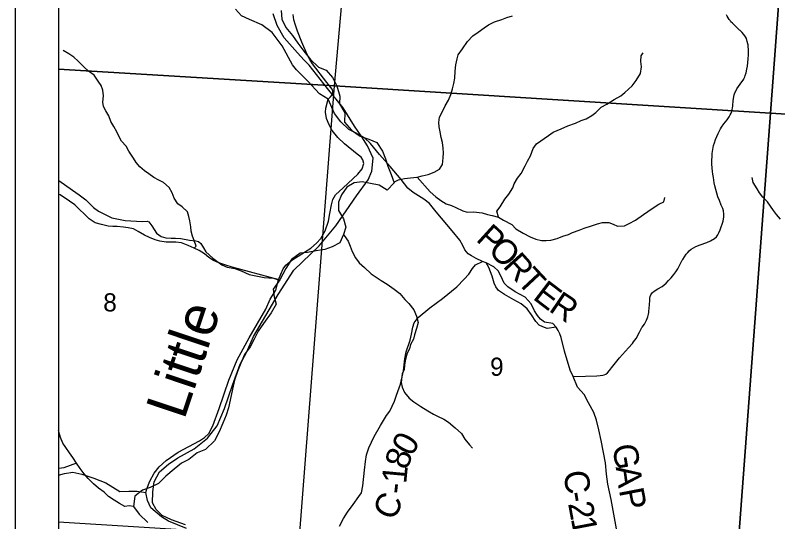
# Model space of a CAD drawing. Extents: x 0 to 34, y 0 to 22.
# Drawn here: x 2 to 3.758, y 17.554 to 18.721 of the extents above; entities that cross this region are included whole.
import ezdxf

# ---------------------------------------------------------------- set-up
doc = ezdxf.new("R2010")
doc.units = 0
for name, color, linetype in [('GM_X_Corporation', 7, 'Continuous'), ('GM_X_County_Road', 7, 'Continuous'), ('GM_X_County_Road_Text', 7, 'Continuous'), ('GM_X_Minor_River', 7, 'Continuous'), ('GM_X_Minor_River_Text', 7, 'Continuous'), ('GM_X_Rail_Line', 7, 'Continuous'), ('GM_X_Section_Text', 7, 'Continuous'), ('GM_X_Township_Road', 7, 'Continuous'), ('SH_Data', 7, 'Continuous')]:
    doc.layers.add(name, color=color, linetype=linetype)

msp = doc.modelspace()

# ---------------------------------------------------------------- linework, layer by layer
at = {"layer": 'GM_X_Corporation'}
for points in [[(3.3441, 14.1), (8.9, 14.1), (8.9, 20.9), (2.1, 20.9), (2.1, 16.1353), (2.1457, 16.065), (2.3447, 15.6926), (2.4297, 15.5215), (2.465, 15.4504), (2.4884, 15.4033), (2.5769, 15.2135), (2.7849, 14.8403), (2.8931, 14.6544), (3.0297, 14.4867), (3.1386, 14.3654), (3.228, 14.2415)], [(2.1, 19.629), (2.1, 18.5966), (2.7366, 18.558), (2.8266, 19.5815)], [(2.8266, 19.5815), (3.8179, 19.5177), (3.742, 18.4953), (2.7366, 18.558)], [(3.8179, 19.5177), (4.8445, 19.4512), (4.7598, 18.4308), (3.742, 18.4953)], [(2.1, 18.5966), (2.1, 17.5535), (2.6553, 17.519), (2.7366, 18.558)], [(3.742, 18.4953), (3.6641, 17.4586), (2.6553, 17.519), (2.7366, 18.558)], [(4.7598, 18.4308), (4.6804, 17.3872), (3.6641, 17.4586), (3.742, 18.4953)]]:
    msp.add_lwpolyline(points, close=True, dxfattribs=at)
msp.add_lwpolyline([(6.7043, 17.4985), (6.7536, 18.2991), (6.7629, 18.3924), (6.7876, 18.7583), (6.824, 19.3005), (6.5423, 19.3229), (5.9419, 19.3649), (5.6539, 19.3859), (5.0201, 19.4401), (4.8375, 19.4557), (3.8692, 19.5228), (3.8201, 19.5262), (3.0215, 19.5789), (2.5886, 19.6074), (2.105, 19.6393), (2.1, 19.6396), (2.1, 16.1353)], dxfattribs=at)
at = {"layer": 'GM_X_County_Road'}
for points in [[(2.7215, 18.5278), (2.7014, 18.5397), (2.6747, 18.5691), (2.6483, 18.5951), (2.6393, 18.6066), (2.6157, 18.6508), (2.5928, 18.6813), (2.569, 18.6989), (2.5402, 18.7113), (2.5221, 18.7197), (2.5078, 18.7347)], [(3.2864, 17.8884), (3.3149, 17.889), (3.3412, 17.8899), (3.3491, 17.8903), (3.3554, 17.8916), (3.3585, 17.8924), (3.3622, 17.894), (3.3658, 17.8968), (3.3704, 17.9024), (3.3751, 17.9086), (3.3935, 17.9312), (3.4144, 17.9544), (3.4234, 17.9642), (3.4257, 17.9679), (3.4316, 17.9762), (3.4397, 17.9902), (3.4453, 18.0012), (3.4457, 18.0018), (3.4511, 18.0093), (3.4556, 18.0184), (3.4586, 18.0256), (3.4604, 18.0319), (3.4611, 18.0355), (3.4615, 18.0383), (3.4626, 18.0533), (3.4633, 18.0643), (3.4637, 18.0689), (3.4645, 18.0729), (3.4658, 18.0766), (3.4677, 18.0791), (3.4699, 18.0819), (3.4732, 18.0847), (3.4821, 18.0903), (3.4921, 18.0959), (3.4963, 18.0992), (3.5008, 18.1031), (3.5069, 18.1094), (3.5128, 18.1156), (3.5189, 18.1232), (3.5237, 18.1295), (3.5278, 18.1363), (3.5357, 18.152), (3.5384, 18.1563), (3.5393, 18.1578), (3.5475, 18.17), (3.5508, 18.1742), (3.5545, 18.1779), (3.5591, 18.1819), (3.5639, 18.1849), (3.5694, 18.1877), (3.5792, 18.1917), (3.5948, 18.197), (3.6037, 18.2007), (3.6129, 18.2063), (3.6172, 18.2102), (3.6202, 18.2145), (3.6227, 18.2198), (3.6259, 18.2266), (3.6323, 18.2464), (3.6338, 18.2562), (3.6341, 18.2626), (3.6332, 18.2699), (3.6315, 18.2756), (3.6281, 18.2834), (3.6238, 18.2943), (3.6206, 18.3022), (3.618, 18.3106), (3.6157, 18.3191), (3.6136, 18.3277), (3.6121, 18.3345), (3.6102, 18.3467), (3.6091, 18.3546), (3.6082, 18.3606), (3.6073, 18.3693), (3.6065, 18.3779), (3.6065, 18.3878), (3.6069, 18.3943), (3.6076, 18.402), (3.6087, 18.4113), (3.6104, 18.4209), (3.6123, 18.4266), (3.6149, 18.4345), (3.6207, 18.4485), (3.6263, 18.4589), (3.6288, 18.4626), (3.6345, 18.4703), (3.6381, 18.475), (3.6419, 18.4802), (3.6462, 18.4869), (3.649, 18.4914), (3.6508, 18.4952), (3.6522, 18.499), (3.6534, 18.5034), (3.6544, 18.507), (3.655, 18.5121), (3.6559, 18.5243), (3.6564, 18.5282), (3.6573, 18.5336), (3.6583, 18.5377), (3.6598, 18.5419), (3.6609, 18.5445), (3.6644, 18.5511), (3.6758, 18.5676), (3.6762, 18.5682), (3.6799, 18.5737), (3.6806, 18.5746), (3.6826, 18.5788), (3.6837, 18.5821), (3.6855, 18.5882), (3.6871, 18.5965), (3.6886, 18.6038), (3.6896, 18.612), (3.6905, 18.6206), (3.6912, 18.6294), (3.6912, 18.6338), (3.6912, 18.6388), (3.6912, 18.6428), (3.6906, 18.6481), (3.69, 18.6528), (3.6896, 18.6551), (3.6882, 18.6606), (3.6862, 18.6671), (3.6842, 18.6708), (3.6823, 18.6738), (3.6795, 18.6777), (3.6763, 18.6814), (3.6715, 18.6859), (3.6703, 18.6869), (3.6587, 18.698), (3.6538, 18.7024), (3.6505, 18.706), (3.6485, 18.7085), (3.6467, 18.7111), (3.6442, 18.715), (3.6422, 18.7185), (3.6403, 18.7218)], [(2.3948, 17.5379), (2.3536, 17.5545), (2.3371, 17.5647), (2.3125, 17.5855), (2.305, 17.6026), (2.3014, 17.6208), (2.3038, 17.6295), (2.3101, 17.6469), (2.3202, 17.6654), (2.3322, 17.6804), (2.3483, 17.695), (2.3758, 17.7136), (2.4247, 17.7402), (2.4366, 17.748), (2.4462, 17.757), (2.4556, 17.7743), (2.4706, 17.8143), (2.4927, 17.8797), (2.5116, 17.9266), (2.5397, 17.9774), (2.5778, 18.0434), (2.588, 18.0668), (2.593, 18.075), (2.6012, 18.0871), (2.6072, 18.1113), (2.6127, 18.1241), (2.6178, 18.1366), (2.624, 18.1452), (2.6382, 18.1564), (2.6814, 18.1839), (2.6948, 18.1955), (2.7045, 18.2067), (2.7146, 18.2241), (2.7221, 18.2464), (2.7258, 18.2642), (2.7291, 18.2842), (2.7327, 18.2964), (2.7385, 18.3069), (2.7566, 18.3233), (2.7904, 18.3544), (2.8001, 18.3672), (2.8036, 18.3789), (2.8019, 18.3873), (2.7978, 18.3938), (2.7888, 18.4011), (2.7596, 18.4243), (2.7443, 18.4394), (2.7309, 18.4555), (2.7243, 18.4685), (2.7181, 18.4827), (2.7156, 18.4975), (2.7165, 18.507), (2.7215, 18.5278)], [(3.0775, 18.1536), (3.0633, 18.1605), (3.0521, 18.1661), (3.0443, 18.1709), (3.037, 18.1802), (3.032, 18.1906), (3.0251, 18.2026), (3.0075, 18.224), (2.9709, 18.2677), (2.9555, 18.2867), (2.9425, 18.297), (2.9176, 18.3122), (2.9054, 18.322), (2.89, 18.3426), (2.8647, 18.3726), (2.8398, 18.4003), (2.8189, 18.4256), (2.8056, 18.4385), (2.7847, 18.4498), (2.7694, 18.4579), (2.7506, 18.4751), (2.736, 18.4942), (2.7215, 18.5278)], [(2.7479, 17.5433), (2.7568, 17.5612), (2.7659, 17.5758), (2.7793, 17.5932), (2.7927, 17.6115), (2.7983, 17.6204), (2.8018, 17.6366), (2.8051, 17.6726), (2.8076, 17.6923), (2.8103, 17.7078), (2.8157, 17.7236), (2.8278, 17.7502), (2.8422, 17.7753), (2.8565, 17.7984), (2.8636, 17.8081), (2.8696, 17.8197), (2.8745, 17.8317), (2.8795, 17.8456), (2.8881, 17.8708), (2.8951, 17.9014), (2.8986, 17.9294), (2.9013, 17.9449), (2.9104, 17.972), (2.9138, 17.9855), (2.9166, 18.0018), (2.9203, 18.0123), (2.929, 18.0242), (2.9558, 18.0466), (2.9852, 18.0678), (3.0186, 18.0953), (3.0354, 18.1123), (3.0463, 18.1241), (3.0547, 18.1371), (3.0617, 18.1453), (3.0775, 18.1536)], [(3.3864, 17.5373), (3.374, 17.6045), (3.3667, 17.6404), (3.3639, 17.6633), (3.3616, 17.6892), (3.3509, 17.741), (3.3455, 17.7651), (3.3401, 17.7877), (3.3347, 17.8054), (3.3224, 17.8278), (3.3118, 17.8468), (3.297, 17.8635), (3.2864, 17.8884), (3.2796, 17.9031), (3.267, 17.9465), (3.2587, 17.9785), (3.256, 17.9866), (3.2523, 17.9945), (3.2474, 18.0021), (3.2269, 17.9987), (3.2168, 18.0024), (3.2082, 18.0069), (3.2005, 18.0154), (3.1903, 18.0306), (3.1805, 18.0441), (3.1668, 18.0559), (3.1496, 18.0648), (3.128, 18.0772), (3.1146, 18.0867), (3.108, 18.0949), (3.1045, 18.1034), (3.0996, 18.1199), (3.0923, 18.1398), (3.0857, 18.1499), (3.0775, 18.1536)]]:
    msp.add_lwpolyline(points, dxfattribs=at)
at = {"layer": 'GM_X_Minor_River'}
for points in [[(2.6132, 18.7321), (2.615, 18.7116), (2.6237, 18.6925), (2.6395, 18.6746), (2.6516, 18.6568), (2.6659, 18.6385), (2.681, 18.6191), (2.6992, 18.6015), (2.717, 18.5947), (2.7313, 18.5776), (2.7419, 18.5581), (2.7482, 18.5345), (2.7478, 18.517), (2.7599, 18.4957), (2.7595, 18.4748), (2.7757, 18.4561), (2.7957, 18.4424), (2.8154, 18.4352), (2.8339, 18.4279), (2.8471, 18.4077), (2.8535, 18.3902), (2.8592, 18.3727), (2.8671, 18.3537), (2.8735, 18.3347), (2.8579, 18.3176), (2.8394, 18.3294), (2.8189, 18.3332), (2.8, 18.3366), (2.7815, 18.3344), (2.7644, 18.3249), (2.7523, 18.307), (2.7454, 18.2899), (2.7457, 18.2708), (2.7567, 18.2518), (2.7627, 18.2324), (2.757, 18.2153), (2.7482, 18.1966), (2.7312, 18.1871), (2.7137, 18.1807), (2.694, 18.178), (2.6743, 18.1742), (2.6569, 18.1727), (2.6372, 18.1583), (2.6239, 18.137), (2.6098, 18.1108), (2.5947, 18.0898), (2.5973, 18.0723), (2.6018, 18.0548), (2.5904, 18.0347), (2.5725, 18.0107), (2.56, 17.9924), (2.5512, 17.9742), (2.5417, 17.9567), (2.5284, 17.9388), (2.5201, 17.9187), (2.5128, 17.8996), (2.506, 17.8802), (2.501, 17.8593), (2.4953, 17.8334), (2.4918, 17.8163), (2.4861, 17.7992), (2.4785, 17.7806), (2.4701, 17.7604), (2.4595, 17.7399), (2.4386, 17.7201), (2.4193, 17.7125), (2.4003, 17.6973), (2.3832, 17.6889), (2.3662, 17.6745), (2.3476, 17.6585), (2.3301, 17.6414), (2.3108, 17.6323), (2.2938, 17.6266), (2.2759, 17.6122), (2.2729, 17.589), (2.2857, 17.5711), (2.3061, 17.5516)], [(2.8735, 18.3347), (2.8743, 18.3367), (2.8841, 18.3416), (2.8974, 18.3446), (2.9113, 18.3462), (2.9268, 18.3481), (2.9382, 18.3507), (2.9522, 18.3542), (2.9658, 18.3591), (2.9783, 18.3663), (2.9851, 18.377), (2.987, 18.3925), (2.9873, 18.4039), (2.987, 18.4149), (2.9851, 18.4274), (2.9824, 18.4388), (2.9802, 18.4525), (2.9779, 18.4635), (2.9771, 18.4737), (2.9787, 18.4863), (2.9836, 18.4961), (2.9911, 18.5121), (2.9995, 18.525), (3.0048, 18.5379), (3.0085, 18.5512), (3.0112, 18.5633), (3.0138, 18.5762), (3.0142, 18.5922), (3.0157, 18.6066), (3.0191, 18.6202), (3.0218, 18.6297), (3.0312, 18.6438), (3.0433, 18.6601), (3.0551, 18.6734), (3.0679, 18.6818), (3.0811, 18.692), (3.0913, 18.6992), (3.105, 18.7061), (3.122, 18.711), (3.1337, 18.7156), (3.1469, 18.7198)], [(2.4127, 18.1842), (2.4169, 18.1887), (2.4127, 18.2016), (2.4086, 18.2119), (2.4055, 18.2229), (2.4048, 18.2331), (2.4025, 18.2468), (2.4006, 18.2571), (2.3972, 18.2681), (2.3851, 18.2791), (2.3753, 18.2866), (2.3662, 18.2992), (2.3617, 18.3117), (2.3549, 18.3242), (2.3417, 18.3352), (2.3311, 18.3405), (2.3198, 18.3473), (2.308, 18.3557), (2.2982, 18.3625), (2.2873, 18.3716), (2.2789, 18.3815), (2.2725, 18.3917), (2.2616, 18.4073), (2.2555, 18.4194), (2.2449, 18.4308), (2.2396, 18.441), (2.2343, 18.4524), (2.2272, 18.4642), (2.2204, 18.4763), (2.2155, 18.4892), (2.209, 18.501), (2.2034, 18.5108), (2.2022, 18.5207), (2.2037, 18.5351), (2.2022, 18.5484), (2.1981, 18.559), (2.1913, 18.5693), (2.1818, 18.5829), (2.169, 18.592), (2.1584, 18.6019), (2.1452, 18.6148), (2.135, 18.6246), (2.1236, 18.6318), (2.1108, 18.6398)], [(3.1143, 18.2552), (3.1109, 18.2696), (3.1181, 18.2795), (3.1287, 18.297), (3.1385, 18.3084), (3.1476, 18.3228), (3.1506, 18.3323), (3.1582, 18.3452), (3.1665, 18.3562), (3.176, 18.3737), (3.1816, 18.3843), (3.1884, 18.3972), (3.1945, 18.4139), (3.2024, 18.4249), (3.2296, 18.4435), (3.2402, 18.4515), (3.2588, 18.4595), (3.2743, 18.4663), (3.292, 18.4724), (3.3049, 18.4781), (3.317, 18.4823), (3.3294, 18.4895), (3.3393, 18.4971), (3.3514, 18.5089), (3.3642, 18.5161), (3.3816, 18.5267), (3.3964, 18.5351), (3.4062, 18.5431), (3.4228, 18.5583), (3.4323, 18.5704), (3.4417, 18.5864), (3.444, 18.6019), (3.4425, 18.6141), (3.4433, 18.6277), (3.4482, 18.6346)], [(2.9268, 18.3481), (2.9567, 18.3136), (2.9699, 18.3022), (2.9816, 18.2938), (2.9941, 18.2859), (3.0058, 18.2821), (3.0157, 18.2775), (3.0323, 18.27), (3.0421, 18.2669), (3.0565, 18.2677), (3.0765, 18.2654), (3.0894, 18.2616), (3.0996, 18.2594), (3.1143, 18.2552), (3.126, 18.2488), (3.1449, 18.2385), (3.1544, 18.2287), (3.1714, 18.2188), (3.1873, 18.2105), (3.2005, 18.2048), (3.2137, 18.2014), (3.2247, 18.2021), (3.2353, 18.2029), (3.25, 18.2063), (3.2632, 18.212), (3.2757, 18.2158), (3.2855, 18.2204), (3.3007, 18.2257), (3.3124, 18.2299), (3.3286, 18.2352), (3.3426, 18.2405), (3.3544, 18.2432), (3.3691, 18.2432), (3.3789, 18.2394), (3.3891, 18.2349), (3.405, 18.2357), (3.416, 18.2406), (3.4307, 18.249), (3.4492, 18.2619), (3.4689, 18.2752), (3.484, 18.2854), (3.4954, 18.2911), (3.4984, 18.301)], [(3.7649, 18.2507), (3.7558, 18.2613), (3.749, 18.2712), (3.7414, 18.2806), (3.7346, 18.2909), (3.7241, 18.3019), (3.7165, 18.3114), (3.7108, 18.3209), (3.7018, 18.3353), (3.6991, 18.347)], [(2.6086, 18.1111), (2.5004, 18.1402), (2.4857, 18.1448), (2.4698, 18.1504), (2.4573, 18.1558), (2.4467, 18.1626), (2.4361, 18.1709), (2.4241, 18.1789), (2.4127, 18.1842), (2.3987, 18.1906), (2.3836, 18.1963), (2.37, 18.1978), (2.3594, 18.1978), (2.3481, 18.1982), (2.3333, 18.2001), (2.3224, 18.2035), (2.3095, 18.2084), (2.2982, 18.2137), (2.2834, 18.2224), (2.2729, 18.2289), (2.2604, 18.2308), (2.2498, 18.2323), (2.2351, 18.2342), (2.2252, 18.2342), (2.2143, 18.2349), (2.1988, 18.2387), (2.1844, 18.2425), (2.1708, 18.252), (2.1602, 18.2618), (2.1477, 18.274), (2.1372, 18.2838), (2.1254, 18.2926), (2.1035, 18.307), (2.1, 18.3084)], [(2.757, 18.2153), (2.7586, 18.2136), (2.7677, 18.2), (2.7726, 18.1886), (2.7771, 18.1761), (2.7847, 18.162), (2.793, 18.1503), (2.8058, 18.1393), (2.821, 18.1248), (2.8327, 18.1173), (2.8436, 18.1097), (2.8576, 18.101), (2.8739, 18.0896), (2.8867, 18.0793), (2.8988, 18.0661), (2.9075, 18.0566), (2.9192, 18.0418), (2.9253, 18.0277), (2.9294, 18.0126), (2.9256, 17.9993), (2.9211, 17.9841), (2.9185, 17.9746), (2.9116, 17.9617), (2.909, 17.9522), (2.9037, 17.9419), (2.8999, 17.9279), (2.898, 17.9146), (2.8969, 17.9047), (2.8924, 17.8941), (2.8901, 17.8748), (2.8924, 17.8634), (2.8976, 17.8512), (2.9082, 17.8387), (2.9192, 17.8296), (2.9351, 17.8194), (2.9517, 17.8091), (2.9642, 17.8015), (2.974, 17.797), (2.9884, 17.7898), (2.9989, 17.783), (3.0148, 17.7701), (3.0288, 17.7572), (3.0371, 17.7439), (3.0477, 17.731), (3.0544, 17.7234)], [(2.2729, 17.589), (2.2629, 17.5905), (2.2531, 17.5886), (2.2402, 17.5958), (2.2285, 17.603), (2.2153, 17.6117), (2.2047, 17.6216), (2.1922, 17.6307), (2.1801, 17.6406), (2.168, 17.6535), (2.1593, 17.6637), (2.1499, 17.6762), (2.1412, 17.6884), (2.1325, 17.7013), (2.1253, 17.7123), (2.1163, 17.7248), (2.1098, 17.735), (2.1045, 17.7475), (2.1008, 17.7608), (2.1, 17.7642)], [(2.1412, 17.6884), (2.1117, 17.6781), (2.1015, 17.6766), (2.1, 17.6763)]]:
    msp.add_lwpolyline(points, dxfattribs=at)
at = {"layer": 'GM_X_Rail_Line'}
msp.add_lwpolyline([(2.3925, 17.5461), (2.3605, 17.5579), (2.3392, 17.5683), (2.3253, 17.5819), (2.3165, 17.5975), (2.3173, 17.6224), (2.3205, 17.6458), (2.3323, 17.6689), (2.3532, 17.6866), (2.3753, 17.7006), (2.4123, 17.7213), (2.4437, 17.7458), (2.466, 17.7747), (2.4829, 17.8148), (2.5008, 17.8685), (2.5185, 17.9165), (2.533, 17.9439), (2.5497, 17.9808), (2.606, 18.0774), (2.6421, 18.133), (2.7012, 18.1892), (2.7396, 18.2353), (2.7869, 18.3045), (2.8136, 18.3416), (2.8221, 18.3615), (2.8253, 18.3919), (2.812, 18.4203), (2.7994, 18.4407), (2.7822, 18.4656), (2.7559, 18.5076), (2.7201, 18.5523), (2.6775, 18.6058), (2.6664, 18.6171), (2.6506, 18.634), (2.6202, 18.6687), (2.6037, 18.697), (2.5949, 18.7243)], dxfattribs=at)
at = {"layer": 'GM_X_Township_Road'}
for points in [[(2.7215, 18.5278), (2.7274, 18.5328), (2.7311, 18.5376), (2.7326, 18.5413), (2.7326, 18.546), (2.7305, 18.5504), (2.7278, 18.5546), (2.7221, 18.5616), (2.7188, 18.5661), (2.6856, 18.6092), (2.6792, 18.6188), (2.6733, 18.6302), (2.6607, 18.6591), (2.6507, 18.6842), (2.6461, 18.6978), (2.6427, 18.7102), (2.6409, 18.7224)], [(2.1, 18.3405), (2.1003, 18.3402), (2.1322, 18.3177), (2.1476, 18.3072), (2.1626, 18.2952), (2.1801, 18.2779), (2.1917, 18.269), (2.2229, 18.2537), (2.2535, 18.2479), (2.2925, 18.2458), (2.3039, 18.246), (2.3084, 18.2445), (2.3151, 18.2356), (2.3258, 18.2184), (2.3363, 18.211), (2.3469, 18.2078), (2.3597, 18.2072), (2.3692, 18.2075), (2.3817, 18.2062), (2.4017, 18.2028), (2.4161, 18.2007), (2.4229, 18.1991), (2.4281, 18.1945), (2.434, 18.1845), (2.4392, 18.1757), (2.456, 18.161), (2.4763, 18.1459), (2.4887, 18.1404), (2.5064, 18.1375), (2.5208, 18.1319), (2.5396, 18.1233), (2.5743, 18.1163), (2.5955, 18.1149), (2.6072, 18.1113)], [(3.2474, 18.0021), (3.24, 18.0102), (3.2205, 18.0137), (3.2113, 18.0208), (3.2043, 18.0286), (3.1978, 18.0395), (3.1895, 18.0557), (3.1756, 18.0709), (3.1528, 18.0833), (3.1357, 18.0952), (3.1276, 18.1038), (3.1197, 18.12), (3.114, 18.132), (3.1037, 18.1414), (3.0857, 18.1499)], [(2.1, 17.6607), (2.1133, 17.6646), (2.1327, 17.6677), (2.1535, 17.6633), (2.181, 17.6537), (2.2092, 17.6431), (2.225, 17.633), (2.2415, 17.6232), (2.262, 17.6241), (2.2813, 17.6242), (2.3014, 17.6208)]]:
    msp.add_lwpolyline(points, dxfattribs=at)
at = {"layer": 'SH_Data'}
for p, q in [((2, 21), (2, 14)), ((2.1, 20.9), (2.1, 14.1))]:
    msp.add_line(p, q, dxfattribs=at)

# ---------------------------------------------------------------- texts
at = {"layer": 'GM_X_County_Road_Text'}
for s, rotation, p in [('P', 317.693, (3.0603, 18.2024)), ('O', 314.3097, (3.088, 18.1772)), ('R', 312.0325, (3.1226, 18.1419)), ('T', 313.018, (3.1545, 18.1064)), ('E', 322.7069, (3.1913, 18.0683)), ('R', 326.0916, (3.2281, 18.0404)), ('0', 60.7773, (2.9145, 17.7018)), ('G', 279.4927, (3.3766, 17.7285)), ('8', 70.8212, (2.904, 17.6711)), ('1', 84.7104, (2.9016, 17.6398)), ('A', 277.7242, (3.3847, 17.6796)), ('C', 276.7483, (3.2647, 17.669)), ('-', 83.5897, (2.8988, 17.6154)), ('-', 279.5736, (3.2706, 17.6196)), ('P', 280.9768, (3.392, 17.6266)), ('C', 64.7071, (2.8733, 17.5537)), ('2', 280.4943, (3.2747, 17.5956)), ('1', 280.8308, (3.2811, 17.5608))]:
    msp.add_text(s, height=0.0568, rotation=rotation, dxfattribs=at).set_placement(p)
at = {"layer": 'GM_X_Minor_River_Text'}
msp.add_text('Little', height=0.09475, rotation=71.5031, dxfattribs=at).set_placement((2.3895, 17.7866))
at = {"layer": 'GM_X_Section_Text'}
for s, p in [('8', (2.203, 18.0382)), ('9', (3.0951, 17.8899))]:
    msp.add_text(s, height=0.0419, rotation=0, dxfattribs=at).set_placement(p)

doc.saveas('drawing.dxf')
